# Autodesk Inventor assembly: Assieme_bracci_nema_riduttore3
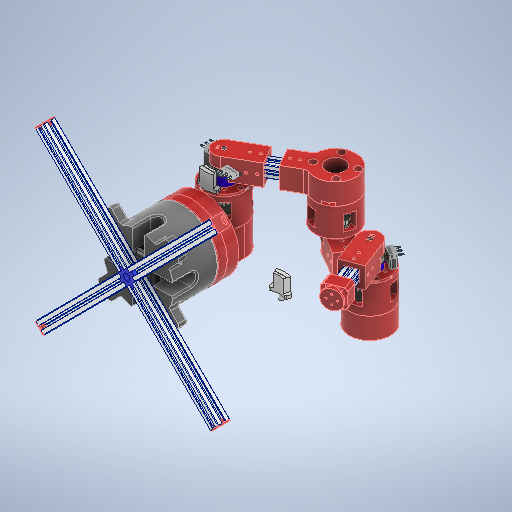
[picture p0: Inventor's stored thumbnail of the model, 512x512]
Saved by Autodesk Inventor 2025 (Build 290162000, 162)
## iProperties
Created: 2026-01
Part Number: Assieme_bracci_nema_riduttore3
Document SubType Name: Assembly
Designer: Ryzen5700u
Author: Ryzen5700u
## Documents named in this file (22)
- C:\Users\Ryzen5700u\Desktop\antropomorfo_nema5\Assieme_bracci_nema_riduttore4.iam
- C:\Users\Ryzen5700u\Desktop\antropomorfo_nema5\blocco_nema_riduttore.iam
- C:\Users\Ryzen5700u\Desktop\antropomorfo_nema5\blocco_nema2.ipt
- C:\Users\Ryzen5700u\Desktop\antropomorfo_nema5\blocco_nema_riduttore2.iam
- C:\Users\Ryzen5700u\Desktop\antropomorfo_nema5\blocco_base.ipt
- C:\Users\Ryzen5700u\Desktop\antropomorfo_nema5\tslot-20x20-5.ipt
- C:\Users\Ryzen5700u\Desktop\antropomorfo_nema5\terminale.ipt
- C:\Users\Ryzen5700u\Desktop\antropomorfo_nema5\NEMA 17HS4401S-PG518.ipt
- C:\Users\Ryzen5700u\Desktop\antropomorfo_nema5\base_01.ipt
- C:\Users\Ryzen5700u\Desktop\antropomorfo_nema5\maschera.ipt
- C:\Users\Ryzen5700u\Desktop\antropomorfo_nema5\ISO 104 - 1 11 50 x 70 x 14.ipt
- C:\Users\Ryzen5700u\Desktop\antropomorfo_nema5\blocco_alto_base.ipt
- C:\Users\Ryzen5700u\Documents\Inventor\Content Center Files\R2025\it-IT\AS 1112 (2)\AS 1112 - M5  Tipo 5.ipt
- C:\Users\Ryzen5700u\Desktop\antropomorfo_nema5\ANSI B18.3.1M - M5x0,8 x 30(1).ipt
- C:\Users\Ryzen5700u\Desktop\antropomorfo_nema5\Assieme_tappo_tslot.iam
- C:\Users\Ryzen5700u\Desktop\antropomorfo_nema5\tslot-20x20-4.ipt
- C:\Users\Ryzen5700u\Documents\Inventor\Content Center Files\R2025\it-IT\ANSI B18.3.1M(6)\ANSI B18.3.1M - M5x0,8 x 16(1).ipt
- C:\Users\Ryzen5700u\Desktop\antropomorfo_nema5\Microswitch-SS-3GL13SL\Microswitch-SS-3GL13SL.iam
- C:\Users\Ryzen5700u\Desktop\antropomorfo_nema5\blocco_finecorsa.ipt
- C:\Users\Ryzen5700u\Desktop\antropomorfo_nema5\blocco_finecorsa2.ipt
- C:\Users\Ryzen5700u\Desktop\antropomorfo_nema5\blocco_finecorsa3.ipt
- C:\Users\Ryzen5700u\Desktop\antropomorfo_nema5\b_sensore_1.ipt
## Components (37 placed, 21 different names)
1. tslot-20x20-4:2 — Coincidente:12, Coincidente:13, Coincidente:14, Coincidente:26, Coincidente:27, Coincidente:28
2. blocco_nema_riduttore2:3 [sub-assembly] — Coincidente:38, Coincidente:41, Coincidente:43, Coincidente:44, Coincidente:45, Coincidente:46, Rotazionale:7
3. blocco_nema_riduttore:2 [sub-assembly]
4. blocco_base:1
5. tslot-20x20-5:1 — Coincidente:32, Coincidente:33, Coincidente:34, Coincidente:35, Coincidente:36, Coincidente:37
6. blocco_nema2:1
7. blocco_nema_riduttore2:4 [sub-assembly]
8. blocco_nema2:2 — Coincidente:35, Coincidente:36, Coincidente:37, Coincidente:38, Coincidente:41, Coincidente:46, Angolo:10
9. tslot-20x20-4:1 — Coincidente:43, Coincidente:44, Coincidente:45, Coincidente:47, Coincidente:48, Coincidente:49
10. terminale:1 — Coincidente:47, Coincidente:48, Coincidente:49
11. NEMA 17HS4401S-PG518:1 — Angolo:3, Coincidente:56, Coincidente:57
12. base_01:1
13. maschera:1
14. UNI ISO 104 1 11 50 x 70 x 14:2 — Rotazionale:4, Coincidente:54
15. blocco_alto_base:2 — Coincidente:54, Coincidente:55, Angolo:5, Coincidente:59
16. Vite forgiata a testa incassata - Metrico M5x0,8 x 30:1
17. Vite forgiata a testa incassata - Metrico M5x0,8 x 30:2
18. Vite forgiata a testa incassata - Metrico M5x0,8 x 30:3
19. Vite forgiata a testa incassata - Metrico M5x0,8 x 30:4
20. Vite forgiata a testa incassata - Metrico M5x0,8 x 16:1
21. Vite forgiata a testa incassata - Metrico M5x0,8 x 16:4
22. Vite forgiata a testa incassata - Metrico M5x0,8 x 16:2
23. Vite forgiata a testa incassata - Metrico M5x0,8 x 16:3
24. Assieme_tappo_tslot:1 [sub-assembly] — Coincidente:60, Coincidente:61
25. Microswitch-SS-3GL13SL:1 [sub-assembly] — Angolo:6, Coincidente:62, Allineato:1, Allineato:2
26. blocco_finecorsa:1 — Rotazionale:5, Coincidente:62, Allineato:1, Allineato:2
27. blocco_finecorsa2:1 — Rotazionale:6, Coincidente:63, Angolo:9, Allineato:3, Allineato:4, Angolo:11
28. Microswitch-SS-3GL13SL:2 [sub-assembly] — Coincidente:63, Angolo:9, Allineato:3, Allineato:4
29. blocco_finecorsa3:1 — Rotazionale:7, Coincidente:64, Coincidente:65, Coincidente:66, Angolo:10
30. Microswitch-SS-3GL13SL:3 [sub-assembly] — Coincidente:64, Coincidente:65, Coincidente:66
31. b_sensore_1:2
32. b_sensore_1:3 — Rotazionale:8, Coincidente:67, Angolo:12
33. Microswitch-SS-3GL13SL:4 [sub-assembly] — Coincidente:67, Angolo:12
34. AS 1112 (2) - Metrico M5  Tipo 5:1
35. AS 1112 (2) - Metrico M5  Tipo 5:2
36. AS 1112 (2) - Metrico M5  Tipo 5:3
37. AS 1112 (2) - Metrico M5  Tipo 5:4
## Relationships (50: Mate 34, Angle 7, RevoluteJoint 5, Flush 4)
- Coincidente:12 [Mate]: tslot-20x20-4:2
- Coincidente:13 [Mate]: tslot-20x20-4:2
- Coincidente:14 [Mate]: tslot-20x20-4:2
- Coincidente:26 [Mate]: tslot-20x20-4:2
- Coincidente:27 [Mate]: tslot-20x20-4:2
- Coincidente:28 [Mate]: tslot-20x20-4:2
- Coincidente:32 [Mate]: tslot-20x20-5:1
- Coincidente:33 [Mate]: tslot-20x20-5:1
- Coincidente:34 [Mate]: tslot-20x20-5:1
- Coincidente:35 [Mate]: tslot-20x20-5:1 ↔ blocco_nema2:2
- Coincidente:36 [Mate]: tslot-20x20-5:1 ↔ blocco_nema2:2
- Coincidente:37 [Mate]: tslot-20x20-5:1 ↔ blocco_nema2:2
- Coincidente:38 [Mate]: blocco_nema_riduttore2:3 ↔ blocco_nema2:2
- Coincidente:41 [Mate]: blocco_nema_riduttore2:3 ↔ blocco_nema2:2
- Coincidente:43 [Mate]: blocco_nema_riduttore2:3 ↔ tslot-20x20-4:1
- Coincidente:44 [Mate]: blocco_nema_riduttore2:3 ↔ tslot-20x20-4:1
- Coincidente:45 [Mate]: blocco_nema_riduttore2:3 ↔ tslot-20x20-4:1
- Coincidente:46 [Mate]: blocco_nema_riduttore2:3 ↔ blocco_nema2:2
- Coincidente:47 [Mate]: tslot-20x20-4:1 ↔ terminale:1
- Coincidente:48 [Mate]: tslot-20x20-4:1 ↔ terminale:1
- Coincidente:49 [Mate]: tslot-20x20-4:1 ↔ terminale:1
- Rotazionale:4 [RevoluteJoint]: UNI ISO 104 1 11 50 x 70 x 14:2
- Angolo:3 [Angle]: NEMA 17HS4401S-PG518:1
- Coincidente:54 [Mate]: UNI ISO 104 1 11 50 x 70 x 14:2 ↔ blocco_alto_base:2
- Coincidente:55 [Mate]: blocco_alto_base:2
- Angolo:5 [Angle]: blocco_alto_base:2
- Coincidente:56 [Mate]: NEMA 17HS4401S-PG518:1
- Coincidente:57 [Mate]: NEMA 17HS4401S-PG518:1
- Coincidente:59 [Mate]: blocco_alto_base:2
- Coincidente:60 [Mate]: Assieme_tappo_tslot:1
- Coincidente:61 [Mate]: Assieme_tappo_tslot:1
- Angolo:6 [Angle]: Microswitch-SS-3GL13SL:1
- Rotazionale:5 [RevoluteJoint]: blocco_finecorsa:1
- Coincidente:62 [Mate]: Microswitch-SS-3GL13SL:1 ↔ blocco_finecorsa:1
- Allineato:1 [Flush]: Microswitch-SS-3GL13SL:1 ↔ blocco_finecorsa:1
- Allineato:2 [Flush]: Microswitch-SS-3GL13SL:1 ↔ blocco_finecorsa:1
- Rotazionale:6 [RevoluteJoint]: blocco_finecorsa2:1
- Coincidente:63 [Mate]: blocco_finecorsa2:1 ↔ Microswitch-SS-3GL13SL:2
- Angolo:9 [Angle]: blocco_finecorsa2:1 ↔ Microswitch-SS-3GL13SL:2
- Allineato:3 [Flush]: blocco_finecorsa2:1 ↔ Microswitch-SS-3GL13SL:2
- Allineato:4 [Flush]: blocco_finecorsa2:1 ↔ Microswitch-SS-3GL13SL:2
- Rotazionale:7 [RevoluteJoint]: blocco_nema_riduttore2:3 ↔ blocco_finecorsa3:1
- Coincidente:64 [Mate]: blocco_finecorsa3:1 ↔ Microswitch-SS-3GL13SL:3
- Coincidente:65 [Mate]: blocco_finecorsa3:1 ↔ Microswitch-SS-3GL13SL:3
- Coincidente:66 [Mate]: blocco_finecorsa3:1 ↔ Microswitch-SS-3GL13SL:3
- Angolo:10 [Angle]: blocco_nema2:2 ↔ blocco_finecorsa3:1
- Angolo:11 [Angle]: blocco_finecorsa2:1
- Rotazionale:8 [RevoluteJoint]: b_sensore_1:3
- Coincidente:67 [Mate]: b_sensore_1:3 ↔ Microswitch-SS-3GL13SL:4
- Angolo:12 [Angle]: b_sensore_1:3 ↔ Microswitch-SS-3GL13SL:4
